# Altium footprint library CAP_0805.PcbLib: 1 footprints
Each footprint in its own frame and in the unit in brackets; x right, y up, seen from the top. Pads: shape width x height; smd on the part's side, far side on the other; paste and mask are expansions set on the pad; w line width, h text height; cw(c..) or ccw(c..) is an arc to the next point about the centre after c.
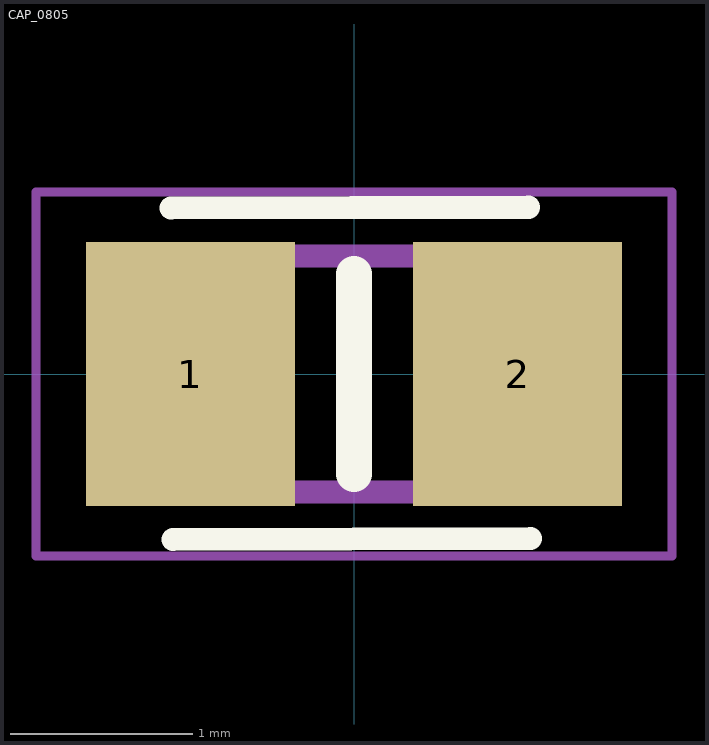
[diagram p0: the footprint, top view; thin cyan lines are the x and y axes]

## CAP_0805 [mm]
pads (2):
  rect 1.15x1.45 smd: 1(-0.9,0) 2(0.9,0)
Top Overlay:
  lines w0.127: -1.007,0.912 0.96,0.917 ; -0.995,-0.91 0.971,-0.905
  lines w0.2: 0,-0.55 0,0.55
Mechanical 13:
  region: -0.5,-0.65 -1,-0.65 -1,0.65 -0.5,0.65
  region: 1,-0.65 0.5,-0.65 0.5,0.65 1,0.65
  lines w0.127: -1,-0.65 1,-0.65 1,0.65 -1,0.65 -1,-0.65
Mechanical 15:
  lines w0.05: -1.75,-1 1.75,-1 1.75,1 -1.75,1 -1.75,-1
3D body "CAP_0805.STEP": height 1.26, standoff 0.01, extent -1,-0.725 1,0.725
